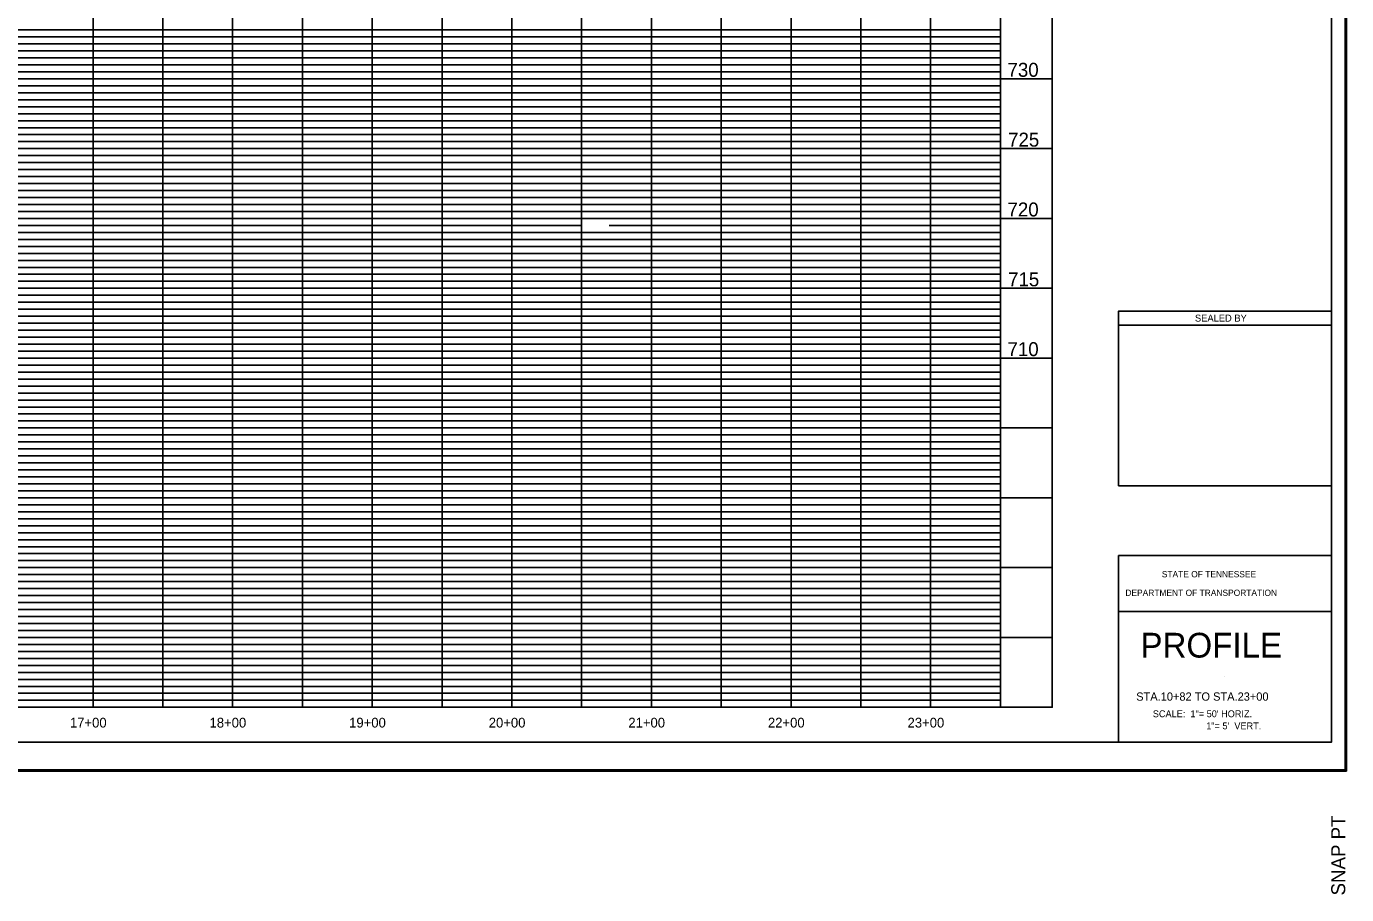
# Model space of a CAD drawing. Extents: x -273 to 1681765, y -325 to 521384.
# Drawn here: x 1680819 to 1681765, y 520141 to 520762 of the extents above; entities that cross this region are included whole.
import ezdxf

# ---------------------------------------------------------------- set-up
doc = ezdxf.new("R2010")
doc.units = 0
for name, color, linetype in [('DESIGN - SCRATCH - User 1', 7, 'Continuous'), ('DESIGN - SHEET - Corner Text', 7, 'Continuous'), ('DESIGN - SHEET - Light Grid', 7, 'Continuous'), ('DESIGN - SHEET - Linework', 7, 'Continuous'), ('DESIGN - SHEET - Plot Shape', 7, 'Continuous')]:
    doc.layers.add(name, color=color, linetype=linetype)

msp = doc.modelspace()

# ---------------------------------------------------------------- linework, layer by layer
at = {"layer": 'DESIGN - SCRATCH - User 1'}
msp.add_line((1681677.98, 520296.56), (1681677.98, 520296.56), dxfattribs=at)
at = {"layer": 'DESIGN - SHEET - Light Grid'}
for p, q in [((1680517.13, 520759.76), (1680867.13, 520759.76)), ((1680867.13, 520759.76), (1681217.13, 520759.76)), ((1681217.13, 520759.76), (1681517.13, 520759.76)), ((1680517.13, 520754.76), (1680867.13, 520754.76)), ((1680517.13, 520749.76), (1680867.13, 520749.76)), ((1680867.13, 520754.76), (1681217.13, 520754.76)), ((1680867.13, 520749.76), (1681217.13, 520749.76)), ((1681217.13, 520754.76), (1681517.13, 520754.76)), ((1681217.13, 520749.76), (1681517.13, 520749.76)), ((1680517.13, 520744.76), (1680867.13, 520744.76)), ((1680517.13, 520739.76), (1680867.13, 520739.76)), ((1680867.13, 520744.76), (1681217.13, 520744.76)), ((1680867.13, 520739.76), (1681217.13, 520739.76)), ((1681217.13, 520744.76), (1681517.13, 520744.76)), ((1681217.13, 520739.76), (1681517.13, 520739.76)), ((1680517.13, 520734.76), (1680867.13, 520734.76)), ((1680517.13, 520729.76), (1680867.13, 520729.76)), ((1680867.13, 520734.76), (1681217.13, 520734.76)), ((1680867.13, 520729.76), (1681217.13, 520729.76)), ((1681217.13, 520734.76), (1681517.13, 520734.76)), ((1681217.13, 520729.76), (1681517.13, 520729.76)), ((1680517.13, 520719.76), (1680867.13, 520719.76)), ((1680867.13, 520719.76), (1681217.13, 520719.76)), ((1681217.13, 520719.76), (1681517.13, 520719.76)), ((1680517.13, 520714.76), (1680867.13, 520714.76)), ((1680517.13, 520709.76), (1680867.13, 520709.76)), ((1680867.13, 520714.76), (1681217.13, 520714.76)), ((1680867.13, 520709.76), (1681217.13, 520709.76)), ((1681217.13, 520714.76), (1681517.13, 520714.76)), ((1681217.13, 520709.76), (1681517.13, 520709.76)), ((1680517.13, 520704.76), (1680867.13, 520704.76)), ((1680517.13, 520699.76), (1680867.13, 520699.76)), ((1680867.13, 520704.76), (1681217.13, 520704.76)), ((1680867.13, 520699.76), (1681217.13, 520699.76)), ((1681217.13, 520704.76), (1681517.13, 520704.76)), ((1681217.13, 520699.76), (1681517.13, 520699.76)), ((1680517.13, 520694.76), (1680867.13, 520694.76)), ((1680867.13, 520694.76), (1681217.13, 520694.76)), ((1681217.13, 520694.76), (1681517.13, 520694.76)), ((1680517.13, 520689.76), (1680867.13, 520689.76)), ((1680517.13, 520684.76), (1680867.13, 520684.76)), ((1680867.13, 520689.76), (1681217.13, 520689.76)), ((1680867.13, 520684.76), (1681217.13, 520684.76)), ((1681217.13, 520689.76), (1681517.13, 520689.76)), ((1681217.13, 520684.76), (1681517.13, 520684.76)), ((1680517.13, 520679.76), (1680867.13, 520679.76)), ((1680867.13, 520679.76), (1681217.13, 520679.76)), ((1681217.13, 520679.76), (1681517.13, 520679.76)), ((1680517.13, 520669.76), (1680867.13, 520669.76)), ((1680517.13, 520664.76), (1680867.13, 520664.76)), ((1680867.13, 520669.76), (1681217.13, 520669.76)), ((1680867.13, 520664.76), (1681217.13, 520664.76)), ((1681217.13, 520669.76), (1681517.13, 520669.76)), ((1681217.13, 520664.76), (1681517.13, 520664.76)), ((1680517.13, 520659.76), (1680867.13, 520659.76)), ((1680517.13, 520654.76), (1680867.13, 520654.76)), ((1680867.13, 520659.76), (1681217.13, 520659.76)), ((1680867.13, 520654.76), (1681217.13, 520654.76)), ((1681217.13, 520659.76), (1681517.13, 520659.76)), ((1681217.13, 520654.76), (1681517.13, 520654.76)), ((1680517.13, 520649.76), (1680867.13, 520649.76)), ((1680517.13, 520644.76), (1680867.13, 520644.76)), ((1680867.13, 520649.76), (1681217.13, 520649.76)), ((1680867.13, 520644.76), (1681217.13, 520644.76)), ((1681217.13, 520649.76), (1681517.13, 520649.76)), ((1681217.13, 520644.76), (1681517.13, 520644.76)), ((1680517.13, 520639.76), (1680867.13, 520639.76)), ((1680517.13, 520634.76), (1680867.13, 520634.76)), ((1680867.13, 520639.76), (1681217.13, 520639.76)), ((1680867.13, 520634.76), (1681217.13, 520634.76)), ((1681217.13, 520639.76), (1681517.13, 520639.76)), ((1681217.13, 520634.76), (1681517.13, 520634.76)), ((1680517.13, 520629.76), (1680867.13, 520629.76)), ((1680867.13, 520629.76), (1681217.13, 520629.76)), ((1681217.13, 520629.76), (1681517.13, 520629.76)), ((1680517.13, 520619.76), (1680867.13, 520619.76)), ((1680517.13, 520614.76), (1680867.13, 520614.76)), ((1680867.13, 520619.76), (1681217.13, 520619.76)), ((1680867.13, 520614.76), (1681217.13, 520614.76)), ((1681217.13, 520614.76), (1681517.13, 520614.76)), ((1681236.76, 520619.76), (1681517.13, 520619.76)), ((1680517.13, 520609.76), (1680867.13, 520609.76)), ((1680867.13, 520609.76), (1681217.13, 520609.76)), ((1681217.13, 520609.76), (1681517.13, 520609.76)), ((1680517.13, 520604.76), (1680867.13, 520604.76)), ((1680517.13, 520599.76), (1680867.13, 520599.76)), ((1680867.13, 520604.76), (1681217.13, 520604.76)), ((1680867.13, 520599.76), (1681217.13, 520599.76)), ((1681217.13, 520604.76), (1681517.13, 520604.76)), ((1681217.13, 520599.76), (1681517.13, 520599.76)), ((1680517.13, 520594.76), (1680867.13, 520594.76)), ((1680517.13, 520589.76), (1680867.13, 520589.76)), ((1680867.13, 520594.76), (1681217.13, 520594.76)), ((1680867.13, 520589.76), (1681217.13, 520589.76)), ((1681217.13, 520594.76), (1681517.13, 520594.76)), ((1681217.13, 520589.76), (1681517.13, 520589.76)), ((1680517.13, 520584.76), (1680867.13, 520584.76)), ((1680517.13, 520579.76), (1680867.13, 520579.76)), ((1680867.13, 520584.76), (1681217.13, 520584.76)), ((1680867.13, 520579.76), (1681217.13, 520579.76)), ((1681217.13, 520584.76), (1681517.13, 520584.76)), ((1681217.13, 520579.76), (1681517.13, 520579.76)), ((1680517.13, 520569.76), (1680867.13, 520569.76)), ((1680867.13, 520569.76), (1681217.13, 520569.76)), ((1681217.13, 520569.76), (1681517.13, 520569.76)), ((1680517.13, 520564.76), (1680867.13, 520564.76)), ((1680517.13, 520559.76), (1680867.13, 520559.76)), ((1680867.13, 520564.76), (1681217.13, 520564.76)), ((1680867.13, 520559.76), (1681217.13, 520559.76)), ((1681217.13, 520564.76), (1681517.13, 520564.76)), ((1681217.13, 520559.76), (1681517.13, 520559.76)), ((1680517.13, 520554.76), (1680867.13, 520554.76)), ((1680517.13, 520549.76), (1680867.13, 520549.76)), ((1680867.13, 520554.76), (1681217.13, 520554.76)), ((1680867.13, 520549.76), (1681217.13, 520549.76)), ((1681217.13, 520554.76), (1681517.13, 520554.76)), ((1681217.13, 520549.76), (1681517.13, 520549.76)), ((1680517.13, 520544.76), (1680867.13, 520544.76)), ((1680517.13, 520539.76), (1680867.13, 520539.76)), ((1680867.13, 520544.76), (1681217.13, 520544.76)), ((1680867.13, 520539.76), (1681217.13, 520539.76)), ((1681217.13, 520544.76), (1681517.13, 520544.76)), ((1681217.13, 520539.76), (1681517.13, 520539.76)), ((1680517.13, 520534.76), (1680867.13, 520534.76)), ((1680517.13, 520529.76), (1680867.13, 520529.76)), ((1680867.13, 520534.76), (1681217.13, 520534.76)), ((1680867.13, 520529.76), (1681217.13, 520529.76)), ((1681217.13, 520534.76), (1681517.13, 520534.76)), ((1681217.13, 520529.76), (1681517.13, 520529.76)), ((1680517.13, 520519.76), (1680867.13, 520519.76)), ((1680517.13, 520514.76), (1680867.13, 520514.76)), ((1680867.13, 520519.76), (1681217.13, 520519.76)), ((1680867.13, 520514.76), (1681217.13, 520514.76)), ((1681217.13, 520519.76), (1681517.13, 520519.76)), ((1681217.13, 520514.76), (1681517.13, 520514.76)), ((1680517.13, 520509.76), (1680867.13, 520509.76)), ((1680517.13, 520504.76), (1680867.13, 520504.76)), ((1680867.13, 520509.76), (1681217.13, 520509.76)), ((1680867.13, 520504.76), (1681217.13, 520504.76)), ((1681217.13, 520509.76), (1681517.13, 520509.76)), ((1681217.13, 520504.76), (1681517.13, 520504.76)), ((1680517.13, 520499.76), (1680867.13, 520499.76)), ((1680517.13, 520494.76), (1680867.13, 520494.76)), ((1680867.13, 520499.76), (1681217.13, 520499.76)), ((1680867.13, 520494.76), (1681217.13, 520494.76)), ((1681217.13, 520499.76), (1681517.13, 520499.76)), ((1681217.13, 520494.76), (1681517.13, 520494.76)), ((1680517.13, 520489.76), (1680867.13, 520489.76)), ((1680517.13, 520484.76), (1680867.13, 520484.76)), ((1680867.13, 520489.76), (1681217.13, 520489.76)), ((1680867.13, 520484.76), (1681217.13, 520484.76)), ((1681217.13, 520489.76), (1681517.13, 520489.76)), ((1681217.13, 520484.76), (1681517.13, 520484.76)), ((1680517.13, 520479.76), (1680867.13, 520479.76)), ((1680867.13, 520479.76), (1681217.13, 520479.76)), ((1681217.13, 520479.76), (1681517.13, 520479.76)), ((1680517.13, 520469.76), (1680867.13, 520469.76)), ((1680517.13, 520464.76), (1680867.13, 520464.76)), ((1680867.13, 520469.76), (1681217.13, 520469.76)), ((1680867.13, 520464.76), (1681217.13, 520464.76)), ((1681217.13, 520469.76), (1681517.13, 520469.76)), ((1681217.13, 520464.76), (1681517.13, 520464.76)), ((1680517.13, 520459.76), (1680867.13, 520459.76)), ((1680517.13, 520454.76), (1680867.13, 520454.76)), ((1680867.13, 520459.76), (1681217.13, 520459.76)), ((1680867.13, 520454.76), (1681217.13, 520454.76)), ((1681217.13, 520459.76), (1681517.13, 520459.76)), ((1681217.13, 520454.76), (1681517.13, 520454.76)), ((1680517.13, 520449.76), (1680867.13, 520449.76)), ((1680517.13, 520444.76), (1680867.13, 520444.76)), ((1680867.13, 520449.76), (1681217.13, 520449.76)), ((1680867.13, 520444.76), (1681217.13, 520444.76)), ((1681217.13, 520449.76), (1681517.13, 520449.76)), ((1681217.13, 520444.76), (1681517.13, 520444.76)), ((1680517.13, 520439.76), (1680867.13, 520439.76)), ((1680517.13, 520434.76), (1680867.13, 520434.76)), ((1680867.13, 520439.76), (1681217.13, 520439.76)), ((1680867.13, 520434.76), (1681217.13, 520434.76)), ((1681217.13, 520439.76), (1681517.13, 520439.76)), ((1681217.13, 520434.76), (1681517.13, 520434.76)), ((1680517.13, 520429.76), (1680867.13, 520429.76)), ((1680867.13, 520429.76), (1681217.13, 520429.76)), ((1681217.13, 520429.76), (1681517.13, 520429.76)), ((1680517.13, 520419.76), (1680867.13, 520419.76)), ((1680867.13, 520419.76), (1681217.13, 520419.76)), ((1681217.13, 520419.76), (1681517.13, 520419.76)), ((1680517.13, 520414.76), (1680867.13, 520414.76)), ((1680517.13, 520409.76), (1680867.13, 520409.76)), ((1680867.13, 520414.76), (1681217.13, 520414.76)), ((1680867.13, 520409.76), (1681217.13, 520409.76)), ((1681217.13, 520414.76), (1681517.13, 520414.76)), ((1681217.13, 520409.76), (1681517.13, 520409.76)), ((1680517.13, 520404.76), (1680867.13, 520404.76)), ((1680517.13, 520399.76), (1680867.13, 520399.76)), ((1680867.13, 520404.76), (1681217.13, 520404.76)), ((1680867.13, 520399.76), (1681217.13, 520399.76)), ((1681217.13, 520404.76), (1681517.13, 520404.76)), ((1681217.13, 520399.76), (1681517.13, 520399.76)), ((1680517.13, 520394.76), (1680867.13, 520394.76)), ((1680517.13, 520389.76), (1680867.13, 520389.76)), ((1680867.13, 520394.76), (1681217.13, 520394.76)), ((1680867.13, 520389.76), (1681217.13, 520389.76)), ((1681217.13, 520394.76), (1681517.13, 520394.76)), ((1681217.13, 520389.76), (1681517.13, 520389.76)), ((1680517.13, 520384.76), (1680867.13, 520384.76)), ((1680517.13, 520379.76), (1680867.13, 520379.76)), ((1680867.13, 520384.76), (1681217.13, 520384.76)), ((1680867.13, 520379.76), (1681217.13, 520379.76)), ((1681217.13, 520384.76), (1681517.13, 520384.76)), ((1681217.13, 520379.76), (1681517.13, 520379.76)), ((1680517.13, 520369.76), (1680867.13, 520369.76)), ((1680867.13, 520369.76), (1681217.13, 520369.76)), ((1681217.13, 520369.76), (1681517.13, 520369.76)), ((1680517.13, 520364.76), (1680867.13, 520364.76)), ((1680517.13, 520359.76), (1680867.13, 520359.76)), ((1680867.13, 520364.76), (1681217.13, 520364.76)), ((1680867.13, 520359.76), (1681217.13, 520359.76)), ((1681217.13, 520364.76), (1681517.13, 520364.76)), ((1681217.13, 520359.76), (1681517.13, 520359.76)), ((1680517.13, 520354.76), (1680867.13, 520354.76)), ((1680517.13, 520349.76), (1680867.13, 520349.76)), ((1680867.13, 520354.76), (1681217.13, 520354.76)), ((1680867.13, 520349.76), (1681217.13, 520349.76)), ((1681217.13, 520354.76), (1681517.13, 520354.76)), ((1681217.13, 520349.76), (1681517.13, 520349.76)), ((1680517.13, 520344.76), (1680867.13, 520344.76)), ((1680867.13, 520344.76), (1681217.13, 520344.76)), ((1681217.13, 520344.76), (1681517.13, 520344.76)), ((1680517.13, 520339.76), (1680867.13, 520339.76)), ((1680517.13, 520334.76), (1680867.13, 520334.76)), ((1680867.13, 520339.76), (1681217.13, 520339.76)), ((1680867.13, 520334.76), (1681217.13, 520334.76)), ((1681217.13, 520339.76), (1681517.13, 520339.76)), ((1681217.13, 520334.76), (1681517.13, 520334.76)), ((1680517.13, 520329.76), (1680867.13, 520329.76)), ((1680867.13, 520329.76), (1681217.13, 520329.76)), ((1681217.13, 520329.76), (1681517.13, 520329.76)), ((1680517.13, 520319.76), (1680867.13, 520319.76)), ((1680517.13, 520314.76), (1680867.13, 520314.76)), ((1680867.13, 520319.76), (1681217.13, 520319.76)), ((1680867.13, 520314.76), (1681217.13, 520314.76)), ((1681217.13, 520319.76), (1681517.13, 520319.76)), ((1681217.13, 520314.76), (1681517.13, 520314.76)), ((1680517.13, 520309.76), (1680867.13, 520309.76)), ((1680517.13, 520304.76), (1680867.13, 520304.76)), ((1680867.13, 520309.76), (1681217.13, 520309.76)), ((1680867.13, 520304.76), (1681217.13, 520304.76)), ((1681217.13, 520309.76), (1681517.13, 520309.76)), ((1681217.13, 520304.76), (1681517.13, 520304.76)), ((1680517.13, 520299.76), (1680867.13, 520299.76)), ((1680517.13, 520294.76), (1680867.13, 520294.76)), ((1680867.13, 520299.76), (1681217.13, 520299.76)), ((1680867.13, 520294.76), (1681217.13, 520294.76)), ((1681217.13, 520299.76), (1681517.13, 520299.76)), ((1681217.13, 520294.76), (1681517.13, 520294.76)), ((1680517.13, 520289.76), (1680867.13, 520289.76)), ((1680517.13, 520284.76), (1680867.13, 520284.76)), ((1680867.13, 520289.76), (1681217.13, 520289.76)), ((1680867.13, 520284.76), (1681217.13, 520284.76)), ((1681217.13, 520289.76), (1681517.13, 520289.76)), ((1681217.13, 520284.76), (1681517.13, 520284.76)), ((1680517.13, 520279.76), (1680867.13, 520279.76)), ((1680867.13, 520279.76), (1681217.13, 520279.76)), ((1681217.13, 520279.76), (1681517.13, 520279.76))]:
    msp.add_line(p, q, dxfattribs=at)
at = {"layer": 'DESIGN - SHEET - Linework'}
for p, q in [((1681765.08, 521320.46), (1681765.08, 520229.06)), ((1680867.13, 520274.76), (1680867.13, 521274.76)), ((1680917.13, 520274.76), (1680917.13, 521274.76)), ((1680967.13, 520274.76), (1680967.13, 521274.76)), ((1681017.13, 520274.76), (1681017.13, 521274.76)), ((1681067.13, 520274.76), (1681067.13, 521274.76)), ((1681117.13, 520274.76), (1681117.13, 521274.76)), ((1681167.13, 520274.76), (1681167.13, 521274.76)), ((1681217.13, 520274.76), (1681217.13, 521274.76)), ((1681267.13, 520274.76), (1681267.13, 521274.76)), ((1681317.13, 520274.76), (1681317.13, 521274.76)), ((1681367.13, 520274.76), (1681367.13, 521274.76)), ((1681417.13, 520274.76), (1681417.13, 521274.76)), ((1681467.13, 520274.76), (1681467.13, 521274.76)), ((1681517.13, 520274.76), (1681517.13, 521274.76)), ((1680180.03, 520724.76), (1681554.23, 520724.76)), ((1680180.03, 520674.76), (1681554.23, 520674.76)), ((1680180.03, 520624.76), (1681554.23, 520624.76)), ((1680180.03, 520574.76), (1681554.23, 520574.76)), ((1681601.73, 520548.41), (1681754.23, 520548.41)), ((1680180.03, 520524.76), (1681554.23, 520524.76)), ((1680180.03, 520474.76), (1681554.23, 520474.76)), ((1680180.03, 520424.76), (1681554.23, 520424.76)), ((1680180.03, 520374.76), (1681554.23, 520374.76)), ((1680180.03, 520324.76), (1681554.23, 520324.76)), ((1680180.03, 520274.76), (1681554.23, 520274.76)), ((1680063.08, 520229.06), (1681765.08, 520229.06))]:
    msp.add_line(p, q, dxfattribs=at)
for points in [[(1680180.03, 521299.76), (1680180.03, 520249.76), (1681754.23, 520249.76), (1681754.23, 521299.76), (1680180.03, 521299.76)], [(1680180.03, 520274.76), (1680180.03, 521274.76), (1681554.23, 521274.76), (1681554.23, 520274.76), (1680182.13, 520274.76)], [(1681601.73, 520249.76), (1681601.73, 520383.41), (1681754.23, 520383.41), (1681754.23, 520343.41), (1681601.73, 520343.41)]]:
    msp.add_lwpolyline(points, dxfattribs=at)
msp.add_lwpolyline([(1681754.23, 520433.41), (1681601.73, 520433.41), (1681601.73, 520558.41), (1681754.23, 520558.41)], close=True, dxfattribs=at)
at = {"layer": 'DESIGN - SHEET - Plot Shape'}
for points in [[(1680064.08, 521319.46), (1681764.08, 521319.46), (1681764.08, 520230.06), (1680064.08, 520230.06)], [(1680094.98, 521299.76), (1681754.23, 521299.76), (1681754.23, 520249.76), (1680094.98, 520249.76)]]:
    msp.add_lwpolyline(points, close=True, dxfattribs=at)

# ---------------------------------------------------------------- texts
at = {"layer": 'DESIGN - SHEET - Corner Text'}
for s, height, p in [('730', 10, (1681522.19, 520726.18)), ('725', 10, (1681522.62, 520676.18)), ('720', 10, (1681522.19, 520626.18)), ('715', 10, (1681522.62, 520576.18)), ('710', 10, (1681522.19, 520526.18)), ('STATE OF TENNESSEE', 4.5, (1681632.73, 520367.81)), ('DEPARTMENT OF TRANSPORTATION', 4.5, (1681606.63, 520354.51)), ('PROFILE', 17.716, (1681617.45, 520310.36)), ('STA.10+82 TO STA.23+00', 5.9055, (1681614.37, 520279.5)), ('17+00', 7, (1680850.58, 520260.26)), ('18+00', 7, (1680950.58, 520260.26)), ('19+00', 7, (1681050.58, 520260.26)), ('20+00', 7, (1681150.58, 520260.26)), ('21+00', 7, (1681250.58, 520260.26)), ('22+00', 7, (1681350.58, 520260.26)), ('23+00', 7, (1681450.58, 520260.26)), ('SCALE:  1"= 50\' HORIZ.', 4.8999, (1681626.28, 520267.66)), ('1"= 5\'  VERT.', 4.8999, (1681664.53, 520259.01))]:
    msp.add_text(s, height=height, dxfattribs=at).set_placement(p)
for s, height, rotation, p in [('SEALED BY', 5, 360, (1681656.46, 520550.91)), ('SNAP PT  ', 10, 90, (1681764.08, 520140.06))]:
    msp.add_text(s, height=height, rotation=rotation, dxfattribs=at).set_placement(p)

doc.saveas('drawing.dxf')
